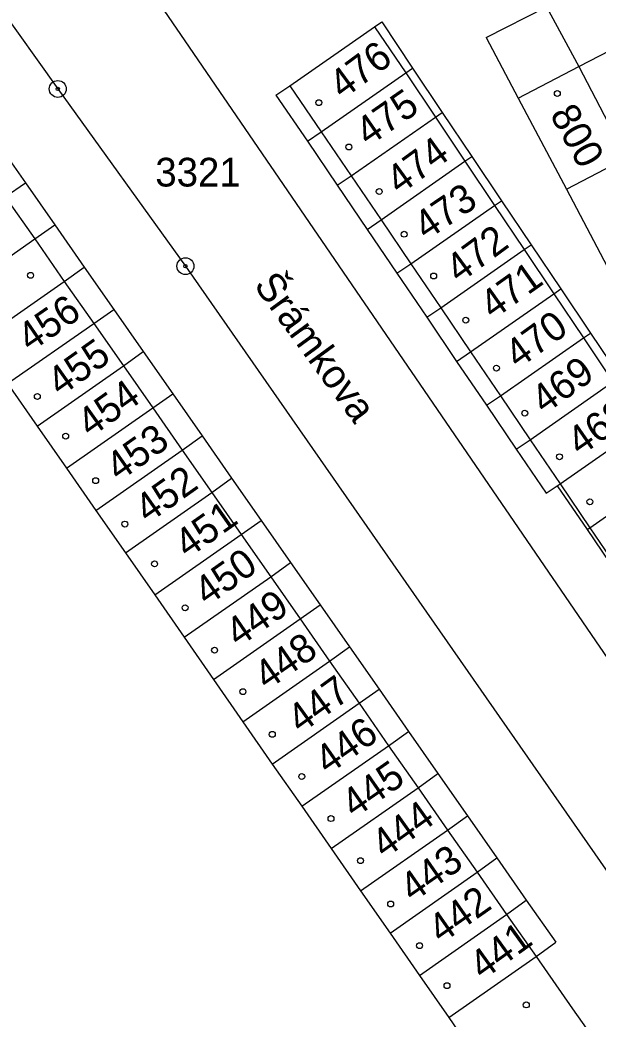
# Model space of a CAD drawing. Extents: x -763205 to -760228, y -1155311 to -1152844.
# Drawn here: x -761873.6 to -761839.3, y -1154690.1 to -1154630.9 of the extents above; entities that cross this region are included whole.
import ezdxf

# ---------------------------------------------------------------- set-up
doc = ezdxf.new("R2010")
doc.units = 0
for name, color, linetype in [('Vrstva 1', 7, 'Continuous'), ('Vrstva 15', 7, 'Continuous'), ('Vrstva 18', 7, 'Continuous'), ('Vrstva 19', 7, 'Continuous'), ('Vrstva 24', 7, 'Continuous'), ('Vrstva 25', 7, 'Continuous'), ('Vrstva 4', 7, 'Continuous')]:
    doc.layers.add(name, color=color, linetype=linetype)

msp = doc.modelspace()

# ---------------------------------------------------------------- linework, layer by layer
at = {"layer": 'Vrstva 1'}
for p, q in [((-761902.13, -1154591.79), (-761871.33, -1154634.99)), ((-761867.91, -1154626.12), (-761828.53, -1154683.64)), ((-761845.92, -1154631.95), (-761842.36, -1154630.13)), ((-761842.36, -1154630.13), (-761840.44, -1154633.66)), ((-761852.54, -1154631.3), (-761852.12, -1154631.02)), ((-761852.12, -1154631.02), (-761850.29, -1154633.76)), ((-761857.56, -1154634.8), (-761852.54, -1154631.3)), ((-761845.92, -1154631.95), (-761844.03, -1154635.53)), ((-761855.71, -1154637.53), (-761850.7, -1154634.04)), ((-761850.7, -1154634.04), (-761850.29, -1154633.76)), ((-761850.29, -1154633.76), (-761848.53, -1154636.38)), ((-761840.44, -1154633.66), (-761837.62, -1154639.08)), ((-761871.33, -1154634.99), (-761863.76, -1154645.49)), ((-761858.39, -1154635.36), (-761857.56, -1154634.8)), ((-761858.39, -1154635.36), (-761856.53, -1154638.09)), ((-761844.03, -1154635.53), (-761841.17, -1154640.92)), ((-761848.94, -1154636.66), (-761848.53, -1154636.38)), ((-761848.53, -1154636.38), (-761846.77, -1154638.99)), ((-761853.94, -1154640.14), (-761848.94, -1154636.66)), ((-761856.53, -1154638.09), (-761855.71, -1154637.53)), ((-761875, -1154638.05), (-761873.25, -1154640.55)), ((-761856.53, -1154638.09), (-761854.76, -1154640.7)), ((-761852.16, -1154642.74), (-761847.19, -1154639.27)), ((-761847.19, -1154639.27), (-761846.77, -1154638.99)), ((-761846.77, -1154638.99), (-761845.02, -1154641.61)), ((-761841.17, -1154640.92), (-761837.62, -1154639.08)), ((-761874.44, -1154641.38), (-761873.25, -1154640.55)), ((-761873.25, -1154640.55), (-761871.5, -1154643.05)), ((-761854.76, -1154640.7), (-761853.94, -1154640.14)), ((-761854.76, -1154640.7), (-761852.99, -1154643.31)), ((-761841.17, -1154640.92), (-761838.36, -1154646.26)), ((-761845.43, -1154641.89), (-761845.02, -1154641.61)), ((-761845.02, -1154641.61), (-761843.26, -1154644.22)), ((-761850.4, -1154645.35), (-761845.43, -1154641.89)), ((-761852.99, -1154643.31), (-761852.16, -1154642.74)), ((-761872.69, -1154643.88), (-761871.5, -1154643.05)), ((-761871.5, -1154643.05), (-761869.76, -1154645.55)), ((-761852.99, -1154643.31), (-761851.22, -1154645.91)), ((-761877.78, -1154647.44), (-761872.69, -1154643.88)), ((-761848.62, -1154647.96), (-761843.68, -1154644.5)), ((-761843.68, -1154644.5), (-761843.26, -1154644.22)), ((-761843.26, -1154644.22), (-761841.51, -1154646.84)), ((-761870.94, -1154646.39), (-761869.76, -1154645.55)), ((-761869.76, -1154645.55), (-761868.01, -1154648.05)), ((-761863.76, -1154645.49), (-761820.39, -1154707.72)), ((-761851.22, -1154645.91), (-761850.4, -1154645.35)), ((-761876.04, -1154649.95), (-761870.94, -1154646.39)), ((-761851.22, -1154645.91), (-761849.45, -1154648.52)), ((-761841.92, -1154647.12), (-761841.51, -1154646.84)), ((-761841.51, -1154646.84), (-761839.75, -1154649.45)), ((-761846.86, -1154650.56), (-761841.92, -1154647.12)), ((-761869.19, -1154648.89), (-761868.01, -1154648.05)), ((-761868.01, -1154648.05), (-761866.26, -1154650.55)), ((-761849.45, -1154648.52), (-761848.62, -1154647.96)), ((-761849.45, -1154648.52), (-761847.68, -1154651.13)), ((-761874.3, -1154652.45), (-761869.19, -1154648.89)), ((-761845.08, -1154653.17), (-761840.16, -1154649.73)), ((-761840.16, -1154649.73), (-761839.75, -1154649.45)), ((-761839.75, -1154649.45), (-761837.99, -1154652.07)), ((-761867.44, -1154651.39), (-761866.26, -1154650.55)), ((-761866.26, -1154650.55), (-761864.51, -1154653.05)), ((-761847.68, -1154651.13), (-761846.86, -1154650.56)), ((-761847.68, -1154651.13), (-761845.91, -1154653.73)), ((-761872.55, -1154654.96), (-761867.44, -1154651.39)), ((-761843.32, -1154655.78), (-761838.41, -1154652.35)), ((-761874.3, -1154652.45), (-761872.55, -1154654.96)), ((-761865.7, -1154653.89), (-761864.51, -1154653.05)), ((-761864.51, -1154653.05), (-761862.77, -1154655.55)), ((-761845.91, -1154653.73), (-761845.08, -1154653.17)), ((-761870.81, -1154657.46), (-761865.7, -1154653.89)), ((-761845.91, -1154653.73), (-761844.14, -1154656.34)), ((-761872.55, -1154654.96), (-761870.81, -1154657.46)), ((-761841.54, -1154658.38), (-761836.65, -1154654.96)), ((-761863.95, -1154656.39), (-761862.77, -1154655.55)), ((-761862.77, -1154655.55), (-761861.02, -1154658.05)), ((-761844.14, -1154656.34), (-761843.32, -1154655.78)), ((-761869.07, -1154659.96), (-761863.95, -1154656.39)), ((-761844.14, -1154656.34), (-761842.37, -1154658.94)), ((-761870.81, -1154657.46), (-761869.07, -1154659.96)), ((-761839.78, -1154660.99), (-761834.9, -1154657.58)), ((-761862.2, -1154658.89), (-761861.02, -1154658.05)), ((-761861.02, -1154658.05), (-761859.27, -1154660.55)), ((-761867.32, -1154662.47), (-761862.2, -1154658.89)), ((-761842.37, -1154658.94), (-761841.71, -1154658.5)), ((-761841.71, -1154658.5), (-761841.54, -1154658.38)), ((-761841.71, -1154658.5), (-761839.94, -1154661.1)), ((-761869.07, -1154659.96), (-761867.32, -1154662.47)), ((-761860.45, -1154661.39), (-761859.27, -1154660.55)), ((-761859.27, -1154660.55), (-761857.52, -1154663.05)), ((-761839.94, -1154661.1), (-761839.78, -1154660.99)), ((-761839.94, -1154661.1), (-761838.17, -1154663.71)), ((-761865.58, -1154664.97), (-761860.45, -1154661.39)), ((-761867.32, -1154662.47), (-761865.58, -1154664.97)), ((-761858.7, -1154663.89), (-761857.52, -1154663.05)), ((-761857.52, -1154663.05), (-761855.78, -1154665.55)), ((-761863.84, -1154667.48), (-761858.7, -1154663.89)), ((-761865.58, -1154664.97), (-761863.84, -1154667.48)), ((-761856.96, -1154666.39), (-761855.78, -1154665.55)), ((-761855.78, -1154665.55), (-761854.03, -1154668.05)), ((-761862.09, -1154669.98), (-761856.96, -1154666.39)), ((-761863.84, -1154667.48), (-761862.09, -1154669.98)), ((-761855.21, -1154668.89), (-761854.03, -1154668.05)), ((-761854.03, -1154668.05), (-761852.28, -1154670.55)), ((-761860.35, -1154672.48), (-761855.21, -1154668.89)), ((-761862.09, -1154669.98), (-761860.35, -1154672.48)), ((-761853.46, -1154671.39), (-761852.28, -1154670.55)), ((-761852.28, -1154670.55), (-761850.54, -1154673.05)), ((-761858.61, -1154674.99), (-761853.46, -1154671.39)), ((-761860.35, -1154672.48), (-761858.61, -1154674.99)), ((-761851.71, -1154673.9), (-761850.54, -1154673.05)), ((-761850.54, -1154673.05), (-761848.79, -1154675.55)), ((-761856.86, -1154677.49), (-761851.71, -1154673.9)), ((-761858.61, -1154674.99), (-761856.86, -1154677.49)), ((-761849.96, -1154676.4), (-761848.79, -1154675.55)), ((-761848.79, -1154675.55), (-761847.04, -1154678.05)), ((-761855.12, -1154680), (-761849.96, -1154676.4)), ((-761856.86, -1154677.49), (-761855.12, -1154680)), ((-761848.22, -1154678.9), (-761847.04, -1154678.05)), ((-761847.04, -1154678.05), (-761845.29, -1154680.55)), ((-761853.38, -1154682.5), (-761848.22, -1154678.9)), ((-761855.12, -1154680), (-761853.38, -1154682.5)), ((-761846.47, -1154681.4), (-761845.29, -1154680.55)), ((-761845.29, -1154680.55), (-761843.55, -1154683.05)), ((-761851.63, -1154685), (-761846.47, -1154681.4)), ((-761853.38, -1154682.5), (-761851.63, -1154685)), ((-761844.72, -1154683.9), (-761843.55, -1154683.05)), ((-761843.55, -1154683.05), (-761841.8, -1154685.54)), ((-761849.89, -1154687.51), (-761844.72, -1154683.9)), ((-761851.63, -1154685), (-761849.89, -1154687.51)), ((-761842.97, -1154686.4), (-761841.8, -1154685.54)), ((-761848.15, -1154690.01), (-761842.97, -1154686.4)), ((-761842.97, -1154686.4), (-761840.81, -1154689.49)), ((-761849.89, -1154687.51), (-761848.15, -1154690.01)), ((-761840.81, -1154689.49), (-761839.42, -1154691.44)), ((-761848.15, -1154690.01), (-761846.06, -1154693.01))]:
    msp.add_line(p, q, dxfattribs=at)
at = {"layer": 'Vrstva 24'}
for centre, radius in [((-761871.33, -1154634.99), 0.5), ((-761871.33, -1154634.99), 0.1), ((-761863.76, -1154645.49), 0.5), ((-761863.76, -1154645.49), 0.1)]:
    msp.add_circle(centre, radius, dxfattribs=at)
at = {"layer": 'Vrstva 25'}
for centre in [(-761841.71, -1154635.26), (-761855.85, -1154635.8), (-761854.07, -1154638.43), (-761852.27, -1154641.07), (-761850.79, -1154643.6), (-761872.94, -1154646.03), (-761849.04, -1154646.07), (-761847.14, -1154648.69), (-761845.32, -1154651.53), (-761872.54, -1154653.21), (-761843.64, -1154654.2), (-761870.86, -1154655.56), (-761841.58, -1154656.78), (-761869.08, -1154658.2), (-761839.78, -1154659.45), (-761867.35, -1154660.77), (-761865.59, -1154663.13), (-761863.78, -1154665.73), (-761862.03, -1154668.24), (-761860.35, -1154670.7), (-761858.61, -1154673.23), (-761856.86, -1154675.73), (-761855.13, -1154678.22), (-761853.38, -1154680.71), (-761851.59, -1154683.28), (-761849.88, -1154685.75), (-761848.25, -1154688.12), (-761843.55, -1154689.26)]:
    msp.add_circle(centre, 0.175, dxfattribs=at)
at = {"layer": 'Vrstva 4'}
for p, q in [((-761852.54, -1154631.3), (-761850.7, -1154634.04)), ((-761840.44, -1154633.66), (-761836.98, -1154631.86)), ((-761850.7, -1154634.04), (-761848.94, -1154636.66)), ((-761844.03, -1154635.53), (-761840.44, -1154633.66)), ((-761857.56, -1154634.8), (-761855.71, -1154637.53)), ((-761848.94, -1154636.66), (-761847.19, -1154639.27)), ((-761855.71, -1154637.53), (-761853.94, -1154640.14)), ((-761847.19, -1154639.27), (-761845.43, -1154641.89)), ((-761853.94, -1154640.14), (-761852.16, -1154642.74)), ((-761874.44, -1154641.38), (-761872.69, -1154643.88)), ((-761845.43, -1154641.89), (-761843.68, -1154644.5)), ((-761852.16, -1154642.74), (-761850.4, -1154645.35)), ((-761872.69, -1154643.88), (-761870.94, -1154646.39)), ((-761843.68, -1154644.5), (-761841.92, -1154647.12)), ((-761850.4, -1154645.35), (-761848.62, -1154647.96)), ((-761870.94, -1154646.39), (-761869.19, -1154648.89)), ((-761841.92, -1154647.12), (-761840.16, -1154649.73)), ((-761848.62, -1154647.96), (-761846.86, -1154650.56)), ((-761869.19, -1154648.89), (-761867.44, -1154651.39)), ((-761840.16, -1154649.73), (-761838.41, -1154652.35)), ((-761846.86, -1154650.56), (-761845.08, -1154653.17)), ((-761867.44, -1154651.39), (-761865.7, -1154653.89)), ((-761845.08, -1154653.17), (-761843.32, -1154655.78)), ((-761865.7, -1154653.89), (-761863.95, -1154656.39)), ((-761843.32, -1154655.78), (-761841.54, -1154658.38)), ((-761863.95, -1154656.39), (-761862.2, -1154658.89)), ((-761862.2, -1154658.89), (-761860.45, -1154661.39)), ((-761841.54, -1154658.38), (-761839.78, -1154660.99)), ((-761839.78, -1154660.99), (-761838, -1154663.6)), ((-761860.45, -1154661.39), (-761858.7, -1154663.89)), ((-761858.7, -1154663.89), (-761856.96, -1154666.39)), ((-761856.96, -1154666.39), (-761855.21, -1154668.89)), ((-761855.21, -1154668.89), (-761853.46, -1154671.39)), ((-761853.46, -1154671.39), (-761851.71, -1154673.9)), ((-761851.71, -1154673.9), (-761849.96, -1154676.4)), ((-761849.96, -1154676.4), (-761848.22, -1154678.9)), ((-761848.22, -1154678.9), (-761846.47, -1154681.4)), ((-761846.47, -1154681.4), (-761844.72, -1154683.9)), ((-761844.72, -1154683.9), (-761842.97, -1154686.4))]:
    msp.add_line(p, q, dxfattribs=at)

# ---------------------------------------------------------------- texts
at = {"layer": 'Vrstva 15'}
msp.add_text('Šrámkova', height=1.7, rotation=306.13135, dxfattribs=at).set_placement((-761859.75, -1154646.632))
at = {"layer": 'Vrstva 18'}
msp.add_text('3321', height=1.7, dxfattribs=at).set_placement((-761865.543, -1154640.77))
at = {"layer": 'Vrstva 19'}
for s, rotation, p in [('476', 36.38282, (-761854.439, -1154635.649)), ('475', 34.66395, (-761852.915, -1154638.435)), ('800', 299.02667, (-761842.185, -1154636.498)), ('474', 35.98175, (-761851.068, -1154641.301)), ('473', 34.09099, (-761849.473, -1154643.997)), ('472', 36.32552, (-761847.529, -1154646.549)), ('471', 35.3515, (-761845.526, -1154648.693)), ('456', 34.54936, (-761872.964, -1154650.625)), ('470', 35.75257, (-761844.037, -1154651.611)), ('455', 35.40879, (-761871.177, -1154653.252)), ('469', 35.63798, (-761842.477, -1154654.312)), ('454', 35.52338, (-761869.397, -1154655.682)), ('468', 34.77854, (-761840.365, -1154656.785)), ('453', 35.12231, (-761867.706, -1154658.293)), ('452', 35.17961, (-761865.986, -1154660.773)), ('451', 35.06502, (-761863.636, -1154662.844)), ('450', 35.06502, (-761862.476, -1154665.664)), ('449', 34.60665, (-761860.625, -1154668.105)), ('448', 34.77854, (-761858.925, -1154670.655)), ('447', 35.86716, (-761856.928, -1154673.231)), ('446', 35.06502, (-761855.316, -1154675.664)), ('445', 34.89313, (-761853.745, -1154678.234)), ('444', 35.63798, (-761851.947, -1154680.632)), ('443', 34.95043, (-761850.285, -1154683.224)), ('442', 35.06502, (-761848.596, -1154685.674)), ('441', 35.80986, (-761846.137, -1154687.831))]:
    msp.add_text(s, height=1.7, rotation=rotation, dxfattribs=at).set_placement(p)

doc.saveas('drawing.dxf')
